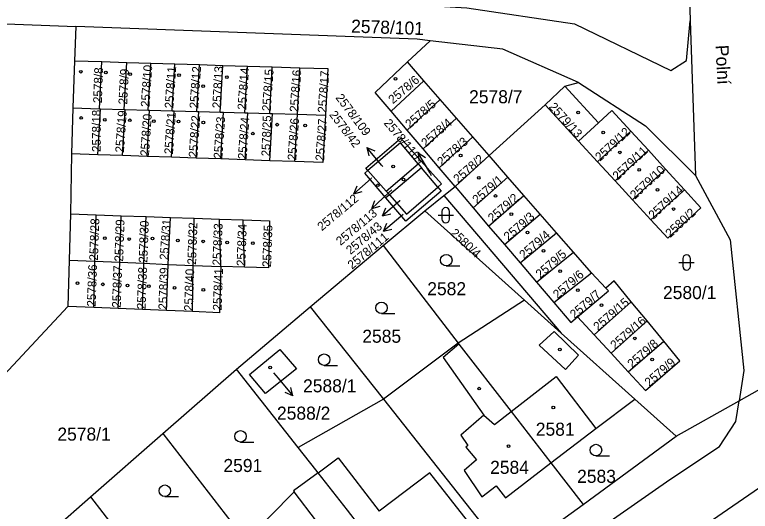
# Model space of a CAD drawing. Extents: x -527335 to -526256, y -1079142 to -1077836.
# Drawn here: x -526700.3 to -526604.5, y -1078355.5 to -1078290.8 of the extents above; entities that cross this region are included whole.
import ezdxf

# ---------------------------------------------------------------- set-up
doc = ezdxf.new("R2010")
doc.units = 0
for name, color, linetype in [('Hranice parcel', 7, 'Continuous'), ('Parcelní čísla', 7, 'Continuous'), ('Pop  PČ popisy', 7, 'Continuous'), ('Vnitřní kresba', 7, 'Continuous'), ('Značky budov', 7, 'Continuous'), ('Značky kultur', 7, 'Continuous')]:
    doc.layers.add(name, color=color, linetype=linetype)

msp = doc.modelspace()

# ---------------------------------------------------------------- linework, layer by layer
at = {"layer": 'Hranice parcel'}
for p, q in [((-526613.4, -1078261.09), (-526612.35, -1078291.6)), ((-526720.03, -1078291.28), (-526692.39, -1078292.33)), ((-526612.35, -1078291.6), (-526611.66, -1078311.76)), ((-526692.39, -1078292.33), (-526692.56, -1078296.81)), ((-526649.16, -1078296.97), (-526646.23, -1078294.21)), ((-526692.56, -1078296.81), (-526692.76, -1078302.96)), ((-526692.56, -1078296.81), (-526688.97, -1078296.92)), ((-526689.31, -1078303.06), (-526688.97, -1078296.92)), ((-526688.97, -1078296.92), (-526685.72, -1078297.02)), ((-526686.06, -1078303.15), (-526685.72, -1078297.02)), ((-526685.72, -1078297.02), (-526682.62, -1078297.12)), ((-526682.96, -1078303.23), (-526682.62, -1078297.12)), ((-526682.62, -1078297.12), (-526679.48, -1078297.22)), ((-526679.81, -1078303.32), (-526679.48, -1078297.22)), ((-526679.48, -1078297.22), (-526676.28, -1078297.32)), ((-526676.61, -1078303.41), (-526676.28, -1078297.32)), ((-526676.28, -1078297.32), (-526673.23, -1078297.41)), ((-526673.56, -1078303.5), (-526673.23, -1078297.41)), ((-526673.23, -1078297.41), (-526670.03, -1078297.51)), ((-526647.04, -1078299.41), (-526649.16, -1078296.97)), ((-526670.36, -1078303.59), (-526670.03, -1078297.51)), ((-526670.03, -1078297.51), (-526666.78, -1078297.61)), ((-526667.12, -1078303.68), (-526666.78, -1078297.61)), ((-526666.78, -1078297.61), (-526663.18, -1078297.72)), ((-526663.52, -1078303.78), (-526663.18, -1078297.72)), ((-526647.04, -1078299.41), (-526651.3, -1078303.4)), ((-526644.92, -1078301.85), (-526647.04, -1078299.41)), ((-526631.23, -1078302.56), (-526628.69, -1078300.14)), ((-526628.69, -1078300.14), (-526626.89, -1078299.64)), ((-526624.28, -1078304.92), (-526628.69, -1078300.14)), ((-526644.92, -1078301.85), (-526649.22, -1078305.85)), ((-526642.8, -1078304.29), (-526644.92, -1078301.85)), ((-526692.76, -1078302.96), (-526692.95, -1078308.93)), ((-526692.76, -1078302.96), (-526689.31, -1078303.06)), ((-526689.49, -1078309.05), (-526689.16, -1078303.06)), ((-526689.31, -1078303.06), (-526689.16, -1078303.06)), ((-526689.16, -1078303.06), (-526686.06, -1078303.15)), ((-526686.29, -1078309.16), (-526685.96, -1078303.15)), ((-526686.06, -1078303.15), (-526685.96, -1078303.15)), ((-526685.96, -1078303.15), (-526682.96, -1078303.23)), ((-526683.1, -1078309.27), (-526682.76, -1078303.24)), ((-526682.96, -1078303.23), (-526682.76, -1078303.24)), ((-526682.76, -1078303.24), (-526679.81, -1078303.32)), ((-526638.55, -1078309.17), (-526631.23, -1078302.56)), ((-526631.23, -1078302.56), (-526626.89, -1078307.29)), ((-526679.9, -1078309.38), (-526679.56, -1078303.33)), ((-526679.81, -1078303.32), (-526679.56, -1078303.33)), ((-526679.56, -1078303.33), (-526676.61, -1078303.41)), ((-526676.7, -1078309.5), (-526676.36, -1078303.42)), ((-526676.61, -1078303.41), (-526676.36, -1078303.42)), ((-526676.36, -1078303.42), (-526673.56, -1078303.5)), ((-526673.56, -1078303.5), (-526673.14, -1078303.51)), ((-526673.48, -1078309.61), (-526673.14, -1078303.51)), ((-526673.14, -1078303.51), (-526670.36, -1078303.59)), ((-526670.36, -1078303.59), (-526669.96, -1078303.6)), ((-526670.3, -1078309.72), (-526669.96, -1078303.6)), ((-526669.96, -1078303.6), (-526667.12, -1078303.68)), ((-526667.12, -1078303.68), (-526666.77, -1078303.69)), ((-526667.11, -1078309.83), (-526666.77, -1078303.69)), ((-526666.77, -1078303.69), (-526663.52, -1078303.78)), ((-526663.86, -1078309.94), (-526663.52, -1078303.78)), ((-526663.52, -1078303.78), (-526659.87, -1078303.88)), ((-526649.22, -1078305.85), (-526651.3, -1078303.4)), ((-526642.8, -1078304.29), (-526647.14, -1078308.3)), ((-526640.68, -1078306.73), (-526642.8, -1078304.29)), ((-526624.28, -1078304.92), (-526626.89, -1078307.29)), ((-526647.14, -1078308.3), (-526649.22, -1078305.85)), ((-526620.09, -1078305.97), (-526624.41, -1078309.98)), ((-526617.79, -1078308.48), (-526620.09, -1078305.97)), ((-526640.68, -1078306.73), (-526645.06, -1078310.75)), ((-526638.55, -1078309.17), (-526640.68, -1078306.73)), ((-526626.89, -1078307.29), (-526624.41, -1078309.98)), ((-526692.95, -1078308.93), (-526693.08, -1078316.77)), ((-526689.49, -1078309.05), (-526692.95, -1078308.93)), ((-526645.06, -1078310.75), (-526647.14, -1078308.3)), ((-526617.79, -1078308.48), (-526622.14, -1078312.45)), ((-526615.55, -1078310.93), (-526617.79, -1078308.48)), ((-526686.29, -1078309.16), (-526689.49, -1078309.05)), ((-526683.1, -1078309.27), (-526686.29, -1078309.16)), ((-526679.9, -1078309.38), (-526683.1, -1078309.27)), ((-526676.7, -1078309.5), (-526679.9, -1078309.38)), ((-526673.48, -1078309.61), (-526676.7, -1078309.5)), ((-526670.3, -1078309.72), (-526673.48, -1078309.61)), ((-526667.11, -1078309.83), (-526670.3, -1078309.72)), ((-526663.86, -1078309.94), (-526667.11, -1078309.83)), ((-526647.8, -1078310.22), (-526647.4, -1078309.88)), ((-526642.98, -1078313.2), (-526638.55, -1078309.17)), ((-526636.1, -1078311.97), (-526638.55, -1078309.17)), ((-526651.94, -1078313.8), (-526647.8, -1078310.22)), ((-526647.34, -1078310.76), (-526651.51, -1078314.29)), ((-526647.8, -1078310.22), (-526647.34, -1078310.76)), ((-526645.22, -1078313.27), (-526647.34, -1078310.76)), ((-526642.98, -1078313.2), (-526645.06, -1078310.75)), ((-526624.41, -1078309.98), (-526622.14, -1078312.45)), ((-526654.33, -1078311.11), (-526651.94, -1078313.8)), ((-526619.86, -1078314.93), (-526615.55, -1078310.93)), ((-526613.1, -1078313.61), (-526615.55, -1078310.93)), ((-526640.62, -1078315.97), (-526636.1, -1078311.97)), ((-526634.01, -1078314.38), (-526636.1, -1078311.97)), ((-526622.14, -1078312.45), (-526619.86, -1078314.93)), ((-526644.44, -1078314.38), (-526642.98, -1078313.2)), ((-526642.98, -1078313.2), (-526640.62, -1078315.97)), ((-526617.46, -1078317.54), (-526613.1, -1078313.61)), ((-526651.51, -1078314.29), (-526651.98, -1078314.69)), ((-526651.51, -1078314.29), (-526651.94, -1078313.8)), ((-526646.9, -1078316.38), (-526644.44, -1078314.38)), ((-526644.44, -1078314.38), (-526629.16, -1078332.29)), ((-526638.6, -1078318.35), (-526634.01, -1078314.38)), ((-526631.88, -1078316.82), (-526634.01, -1078314.38)), ((-526619.86, -1078314.93), (-526617.46, -1078317.54)), ((-526652.33, -1078320.86), (-526646.9, -1078316.38)), ((-526633.94, -1078328), (-526646.9, -1078316.38)), ((-526640.62, -1078315.97), (-526638.6, -1078318.35)), ((-526693.08, -1078316.77), (-526693.26, -1078322.79)), ((-526693.08, -1078316.77), (-526689.74, -1078316.89)), ((-526689.91, -1078322.93), (-526689.74, -1078316.89)), ((-526689.74, -1078316.89), (-526686.49, -1078317)), ((-526686.65, -1078323.07), (-526686.49, -1078317)), ((-526686.49, -1078317), (-526683.2, -1078317.11)), ((-526683.5, -1078323.2), (-526683.2, -1078317.11)), ((-526683.2, -1078317.11), (-526680.06, -1078317.22)), ((-526680.35, -1078323.34), (-526680.06, -1078317.22)), ((-526680.06, -1078317.22), (-526676.96, -1078317.33)), ((-526677.1, -1078323.48), (-526676.96, -1078317.33)), ((-526676.96, -1078317.33), (-526673.67, -1078317.44)), ((-526673.67, -1078317.44), (-526670.57, -1078317.55)), ((-526673.47, -1078323.63), (-526673.67, -1078317.44)), ((-526670.39, -1078323.7), (-526670.57, -1078317.55)), ((-526636.54, -1078320.77), (-526631.88, -1078316.82)), ((-526629.77, -1078319.23), (-526631.88, -1078316.82)), ((-526638.6, -1078318.35), (-526636.54, -1078320.77)), ((-526634.51, -1078323.15), (-526629.77, -1078319.23)), ((-526627.56, -1078321.77), (-526629.77, -1078319.23)), ((-526661.84, -1078328.88), (-526652.33, -1078320.86)), ((-526652.33, -1078320.86), (-526642.59, -1078333.62)), ((-526636.54, -1078320.77), (-526634.51, -1078323.15)), ((-526632.38, -1078325.66), (-526627.56, -1078321.77)), ((-526625.21, -1078324.46), (-526627.56, -1078321.77)), ((-526693.26, -1078322.79), (-526693.43, -1078328.83)), ((-526693.26, -1078322.79), (-526689.91, -1078322.93)), ((-526690.03, -1078328.97), (-526689.91, -1078322.93)), ((-526689.91, -1078322.93), (-526686.65, -1078323.07)), ((-526686.87, -1078329.1), (-526686.65, -1078323.07)), ((-526686.65, -1078323.07), (-526683.5, -1078323.2)), ((-526683.71, -1078329.22), (-526683.5, -1078323.2)), ((-526683.5, -1078323.2), (-526680.35, -1078323.34)), ((-526680.56, -1078329.34), (-526680.35, -1078323.34)), ((-526680.35, -1078323.34), (-526677.1, -1078323.48)), ((-526634.51, -1078323.15), (-526632.38, -1078325.66)), ((-526677.2, -1078329.49), (-526677.1, -1078323.48)), ((-526677.1, -1078323.48), (-526673.47, -1078323.63)), ((-526670.39, -1078323.7), (-526673.47, -1078323.63)), ((-526630.12, -1078328.32), (-526625.21, -1078324.46)), ((-526623.32, -1078326.45), (-526625.21, -1078324.46)), ((-526632.38, -1078325.66), (-526630.12, -1078328.32)), ((-526633.94, -1078328), (-526642.59, -1078333.62)), ((-526629.16, -1078332.29), (-526633.94, -1078328)), ((-526693.43, -1078328.83), (-526701.71, -1078337.73)), ((-526690.03, -1078328.97), (-526693.43, -1078328.83)), ((-526686.87, -1078329.1), (-526690.03, -1078328.97)), ((-526683.71, -1078329.22), (-526686.87, -1078329.1)), ((-526671.45, -1078336.99), (-526661.84, -1078328.88)), ((-526661.84, -1078328.88), (-526652.31, -1078340.92)), ((-526624.86, -1078332.51), (-526620.02, -1078328.21)), ((-526617.96, -1078330.71), (-526620.02, -1078328.21)), ((-526680.56, -1078329.34), (-526683.71, -1078329.22)), ((-526677.2, -1078329.49), (-526680.56, -1078329.34)), ((-526627.02, -1078330.16), (-526624.86, -1078332.51)), ((-526617.96, -1078330.71), (-526622.65, -1078334.92)), ((-526615.79, -1078333.35), (-526617.96, -1078330.71)), ((-526629.16, -1078332.29), (-526619.54, -1078340.92)), ((-526624.86, -1078332.51), (-526622.65, -1078334.92)), ((-526642.59, -1078333.62), (-526652.31, -1078340.92)), ((-526620.42, -1078337.34), (-526615.79, -1078333.35)), ((-526622.65, -1078334.92), (-526620.42, -1078337.34)), ((-526681.04, -1078345.37), (-526671.45, -1078336.99)), ((-526663.41, -1078347.2), (-526671.45, -1078336.99)), ((-526652.31, -1078340.92), (-526663.41, -1078347.2)), ((-526652.31, -1078340.92), (-526635.98, -1078361.55)), ((-526619.54, -1078340.92), (-526614.17, -1078345.74)), ((-526614.17, -1078345.74), (-526605.97, -1078341.1)), ((-526690.48, -1078353.62), (-526681.04, -1078345.37)), ((-526681.04, -1078345.37), (-526670.21, -1078359.37)), ((-526626.29, -1078354.62), (-526614.17, -1078345.74)), ((-526630.48, -1078349.21), (-526626.29, -1078354.62)), ((-526699.79, -1078361.79), (-526690.48, -1078353.62)), ((-526690.48, -1078353.62), (-526683.67, -1078362.36)), ((-526635.98, -1078361.55), (-526626.29, -1078354.62))]:
    msp.add_line(p, q, dxfattribs=at)
for points in [[(-526695.92, -1078285.82), (-526696.17, -1078286.6), (-526641.44, -1078289.9), (-526627.42, -1078292.02), (-526614.86, -1078298.09), (-526612.81, -1078296.77), (-526612.35, -1078291.6)], [(-526646.23, -1078294.21), (-526647.91, -1078294.02), (-526692.39, -1078292.33)], [(-526626.89, -1078299.64), (-526636.74, -1078295.3), (-526646.23, -1078294.21)], [(-526651.3, -1078303.4), (-526653.38, -1078300.95), (-526649.16, -1078296.97)], [(-526663.18, -1078297.72), (-526659.54, -1078297.84), (-526659.87, -1078303.88)], [(-526626.89, -1078299.64), (-526618.17, -1078305.28), (-526611.66, -1078311.76)], [(-526659.87, -1078303.88), (-526660.21, -1078310.07), (-526663.86, -1078309.94)], [(-526620.09, -1078305.97), (-526622.54, -1078303.29), (-526624.28, -1078304.92)], [(-526654.33, -1078311.11), (-526654.59, -1078310.82), (-526650.04, -1078306.89), (-526647.4, -1078309.88)], [(-526647.8, -1078310.22), (-526650.1, -1078307.51), (-526654.33, -1078311.11)], [(-526647.4, -1078309.88), (-526644.75, -1078312.86), (-526645.22, -1078313.27)], [(-526651.98, -1078314.69), (-526654.74, -1078311.46), (-526654.33, -1078311.11)], [(-526611.66, -1078311.76), (-526607.16, -1078320.16), (-526605.36, -1078337.18), (-526605.97, -1078341.1)], [(-526645.22, -1078313.27), (-526644.77, -1078313.8), (-526649.38, -1078317.72), (-526651.98, -1078314.69)], [(-526651.51, -1078314.29), (-526649.29, -1078316.79), (-526645.22, -1078313.27)], [(-526613.1, -1078313.61), (-526610.95, -1078315.97), (-526615.26, -1078319.93), (-526617.46, -1078317.54)], [(-526670.57, -1078317.55), (-526667.15, -1078317.67), (-526667.26, -1078323.78), (-526670.39, -1078323.7)], [(-526673.47, -1078323.63), (-526673.67, -1078329.63), (-526677.2, -1078329.49)], [(-526538.39, -1078327.72), (-526540.03, -1078327.15), (-526546.04, -1078326.1), (-526550.79, -1078326.44), (-526558.7, -1078329.17), (-526588.71, -1078343.39), (-526596.49, -1078347.76), (-526612.22, -1078358.58), (-526630.45, -1078371.95), (-526674.07, -1078406.52), (-526700.09, -1078429.86), (-526748.62, -1078475.19)], [(-526620.02, -1078328.21), (-526622.27, -1078325.47), (-526623.32, -1078326.45)], [(-526627.02, -1078330.16), (-526623.01, -1078326.8), (-526623.32, -1078326.45)], [(-526630.12, -1078328.32), (-526627.91, -1078330.91), (-526627.02, -1078330.16)], [(-526642.59, -1078333.62), (-526642.49, -1078333.75), (-526635.67, -1078342.52), (-526630.48, -1078349.21)], [(-526620.42, -1078337.34), (-526618.18, -1078339.77), (-526613.7, -1078335.9), (-526615.79, -1078333.35)], [(-526663.65, -1078336.93), (-526667.65, -1078340.17), (-526669.74, -1078337.68), (-526665.81, -1078334.44), (-526663.65, -1078336.93)], [(-526605.97, -1078341.1), (-526595.52, -1078335.19), (-526593.56, -1078334.08)], [(-526630.48, -1078349.21), (-526624.62, -1078344.7), (-526619.54, -1078340.92)], [(-526660.83, -1078350.48), (-526661.12, -1078350.11), (-526663.41, -1078347.2)], [(-526660.83, -1078350.48), (-526664.04, -1078352.82), (-526663.93, -1078352.97), (-526670.21, -1078359.37)], [(-526646.41, -1078369.36), (-526650.13, -1078364.49), (-526655.4, -1078357.43), (-526656.98, -1078355.37), (-526660.83, -1078350.48)]]:
    msp.add_lwpolyline(points, dxfattribs=at)
at = {"layer": 'Pop  PČ popisy'}
for p, q in [((-526652.54, -1078310.4), (-526654.469, -1078308.101)), ((-526654.469, -1078308.101), (-526653.442, -1078308.546)), ((-526654.469, -1078308.101), (-526654.209, -1078309.19)), ((-526646.27, -1078311.39), (-526647.77, -1078308.791)), ((-526647.77, -1078308.791), (-526646.836, -1078309.408)), ((-526647.77, -1078308.791), (-526647.703, -1078309.909)), ((-526652.37, -1078310.6), (-526652.54, -1078310.4)), ((-526646.04, -1078311.79), (-526646.27, -1078311.39)), ((-526653.92, -1078312.15), (-526656.15, -1078314.158)), ((-526653.85, -1078312.08), (-526653.92, -1078312.15)), ((-526656.15, -1078314.158), (-526655.741, -1078313.116)), ((-526651.22, -1078313.64), (-526651.63, -1078314.02)), ((-526656.15, -1078314.158), (-526655.071, -1078313.86)), ((-526651.63, -1078314.02), (-526653.825, -1078316.067)), ((-526653.825, -1078316.067), (-526653.434, -1078315.017)), ((-526650.16, -1078315.05), (-526652.425, -1078317.019)), ((-526650.11, -1078315.01), (-526650.16, -1078315.05)), ((-526653.825, -1078316.067), (-526652.751, -1078315.75)), ((-526652.425, -1078317.019), (-526651.998, -1078315.984)), ((-526652.425, -1078317.019), (-526651.341, -1078316.74)), ((-526650.02, -1078317.09), (-526652.319, -1078319.019)), ((-526649.74, -1078316.86), (-526650.02, -1078317.09)), ((-526652.319, -1078319.019), (-526651.874, -1078317.992)), ((-526652.319, -1078319.019), (-526651.23, -1078318.759)), ((-526666.61, -1078337.48), (-526666.03, -1078338.17)), ((-526666.03, -1078338.17), (-526664.101, -1078340.469)), ((-526664.101, -1078340.469), (-526664.361, -1078339.38)), ((-526664.101, -1078340.469), (-526665.128, -1078340.024))]:
    msp.add_line(p, q, dxfattribs=at)
at = {"layer": 'Vnitřní kresba'}
for p, q in [((-526632.02, -1078333.85), (-526630.07, -1078332.1)), ((-526630.07, -1078332.1), (-526626.89, -1078335.15)), ((-526642.49, -1078333.75), (-526644.53, -1078335.48)), ((-526628.6, -1078337.05), (-526632.02, -1078333.85)), ((-526644.53, -1078335.48), (-526639.22, -1078342.99)), ((-526626.89, -1078335.15), (-526628.6, -1078337.05)), ((-526635.67, -1078342.52), (-526629.79, -1078337.93)), ((-526629.79, -1078337.93), (-526624.62, -1078344.7)), ((-526606.39, -1078343.8), (-526605.97, -1078341.1)), ((-526637.83, -1078344.21), (-526635.67, -1078342.52)), ((-526639.22, -1078342.99), (-526642.22, -1078345.58)), ((-526639.22, -1078342.99), (-526637.83, -1078344.21)), ((-526608.53, -1078347.08), (-526606.39, -1078343.8)), ((-526642.22, -1078345.58), (-526641.31, -1078346.93)), ((-526641.31, -1078346.93), (-526641.57, -1078347.13)), ((-526641.57, -1078347.13), (-526640.18, -1078348.82)), ((-526615, -1078351.38), (-526608.53, -1078347.08)), ((-526660.83, -1078350.48), (-526658.21, -1078348.55)), ((-526658.21, -1078348.55), (-526652.85, -1078355.49)), ((-526640.18, -1078348.82), (-526641.81, -1078350.21)), ((-526636.41, -1078353.77), (-526630.48, -1078349.21)), ((-526646.28, -1078350.48), (-526652.85, -1078355.49)), ((-526640.86, -1078357.35), (-526646.28, -1078350.48)), ((-526641.81, -1078350.21), (-526639.49, -1078353.6)), ((-526635.99, -1078365.95), (-526615, -1078351.38)), ((-526661.04, -1078356.81), (-526663.93, -1078352.97)), ((-526639.49, -1078353.6), (-526637.62, -1078352.18)), ((-526637.62, -1078352.18), (-526636.41, -1078353.77))]:
    msp.add_line(p, q, dxfattribs=at)
at = {"layer": 'Značky budov'}
for centre in [(-526691.717, -1078298.239), (-526688.477, -1078298.339), (-526685.287, -1078298.559), (-526678.937, -1078298.699), (-526672.687, -1078298.949), (-526650.727, -1078299.179), (-526675.787, -1078300.129), (-526691.667, -1078304.269), (-526626.957, -1078303.559), (-526688.617, -1078304.519), (-526685.337, -1078304.569), (-526682.227, -1078304.669), (-526679.017, -1078304.719), (-526675.767, -1078304.869), (-526666.147, -1078305.139), (-526662.517, -1078305.249), (-526623.667, -1078306.149), (-526669.327, -1078306.309), (-526642.247, -1078309.169), (-526621.507, -1078308.749), (-526651.027, -1078310.599), (-526618.977, -1078311.009), (-526649.697, -1078312.279), (-526639.897, -1078312.069), (-526653.027, -1078313.039), (-526616.597, -1078313.629), (-526637.707, -1078314.429), (-526635.647, -1078316.789), (-526614.507, -1078316.129), (-526633.547, -1078319.179), (-526688.587, -1078319.919), (-526685.417, -1078320.039), (-526682.381, -1078319.977), (-526679.077, -1078320.239), (-526675.797, -1078320.339), (-526672.667, -1078320.499), (-526669.307, -1078320.579), (-526631.457, -1078321.589), (-526629.287, -1078324.209), (-526692.167, -1078325.779), (-526688.867, -1078325.939), (-526685.647, -1078326.089), (-526682.857, -1078326.179), (-526679.507, -1078326.399), (-526675.767, -1078326.659), (-526626.977, -1078326.709), (-526623.897, -1078328.649), (-526619.557, -1078332.979), (-526629.337, -1078334.419), (-526617.287, -1078335.729), (-526667.067, -1078336.769), (-526639.837, -1078339.529), (-526630.177, -1078341.969), (-526635.997, -1078347.029)]:
    msp.add_circle(centre, 0.175, dxfattribs=at)
at = {"layer": 'Značky kultur'}
for p, q in [((-526644.691, -1078316.441), (-526644.691, -1078317.442)), ((-526643.689, -1078317.442), (-526643.689, -1078316.441)), ((-526645.191, -1078316.941), (-526643.189, -1078316.941)), ((-526613.821, -1078323.081), (-526611.819, -1078323.081)), ((-526613.321, -1078322.581), (-526613.321, -1078323.582)), ((-526612.319, -1078323.582), (-526612.319, -1078322.581)), ((-526644.123, -1078323.54), (-526642.373, -1078323.54)), ((-526652.563, -1078329.75), (-526650.813, -1078329.75)), ((-526660.033, -1078336.5), (-526658.283, -1078336.5)), ((-526670.923, -1078346.49), (-526669.173, -1078346.49)), ((-526624.623, -1078348.28), (-526622.873, -1078348.28)), ((-526680.773, -1078353.58), (-526679.023, -1078353.58))]:
    msp.add_line(p, q, dxfattribs=at)
for centre in [(-526644.123, -1078322.79), (-526652.563, -1078329), (-526660.033, -1078335.75), (-526670.923, -1078345.74), (-526624.623, -1078347.53), (-526680.773, -1078352.83)]:
    msp.add_circle(centre, 0.75, dxfattribs=at)
for centre, start, end in [((-526644.19, -1078316.441), 0, 180), ((-526644.19, -1078317.441), 180, 359.98789), ((-526612.82, -1078322.581), 0, 180), ((-526612.82, -1078323.581), 180, 359.98789)]:
    msp.add_arc(centre, 0.5, start, end, dxfattribs=at)

# ---------------------------------------------------------------- texts
at = {"layer": 'Parcelní čísla'}
for s, height, rotation, p in [('2578/101', 1.7, 358, (-526656.539, -1078293.139)), ('2578/10', 1.14, 86, (-526682.791, -1078302.889)), ('2578/8', 1.139, 88, (-526688.988, -1078302.353)), ('2578/9', 1.139, 87, (-526685.697, -1078302.541)), ('2578/11', 1.14, 86, (-526679.681, -1078303.069)), ('2578/12', 1.14, 86, (-526676.441, -1078303.069)), ('2578/13', 1.139, 87, (-526673.465, -1078303.037)), ('2578/14', 1.14, 86, (-526670.191, -1078303.249)), ('2578/15', 1.14, 86, (-526666.991, -1078303.429)), ('2578/16', 1.14, 86, (-526663.391, -1078303.529)), ('2578/17', 1.14, 86, (-526659.741, -1078303.629)), ('2578/6', 1.139, 40, (-526651.08, -1078302.489)), ('2578/109', 1.14, 307, (-526658.605, -1078301.643)), ('2578/5', 1.14, 41, (-526648.866, -1078305.68)), ('2579/13', 1.14, 312, (-526630.823, -1078302.871)), ('2578/18', 1.139, 90, (-526689.13, -1078308.701)), ('2578/19', 1.14, 86, (-526686.121, -1078308.819)), ('2578/20', 1.14, 86, (-526682.861, -1078309.269)), ('2578/21', 1.14, 86, (-526679.731, -1078309.039)), ('2578/22', 1.14, 86, (-526676.551, -1078309.459)), ('2578/23', 1.14, 86, (-526673.301, -1078309.619)), ('2578/25', 1.1, 88, (-526667.107, -1078309.271)), ('2578/42', 1.14, 307, (-526659.425, -1078303.843)), ('2578/24', 1.14, 86, (-526670.141, -1078309.689)), ('2578/26', 1.14, 86, (-526663.671, -1078309.819)), ('2578/27', 1.14, 86, (-526660.041, -1078309.889)), ('2578/110', 1.14, 310, (-526652.326, -1078304.966)), ('2578/4', 1.14, 41, (-526646.786, -1078308.13)), ('2579/12', 1.14, 43, (-526624.091, -1078309.976)), ('2578/3', 1.14, 41, (-526644.706, -1078310.58)), ('2579/11', 1.14, 43, (-526621.821, -1078312.446)), ('2578/2', 1.14, 41, (-526642.596, -1078312.83)), ('2579/10', 1.14, 43, (-526619.541, -1078314.926)), ('2579/1', 1.14, 41, (-526640.116, -1078315.53)), ('2579/14', 1.14, 43, (-526617.141, -1078317.536)), ('2578/112', 1.14, 40, (-526660.323, -1078319.036)), ('2579/2', 1.14, 41, (-526638.096, -1078317.91)), ('2578/113', 1.14, 40, (-526657.893, -1078320.946)), ('2579/3', 1.14, 41, (-526636.036, -1078320.33)), ('2580/2', 1.14, 43, (-526614.941, -1078319.926)), ('2578/28', 1.14, 88, (-526689.5, -1078322.869)), ('2578/29', 1.14, 88, (-526686.22, -1078322.999)), ('2578/31', 1.1, 86, (-526680.374, -1078322.785)), ('2578/30', 1.14, 88, (-526683.06, -1078323.159)), ('2578/32', 1.14, 88, (-526676.72, -1078323.399)), ('2578/33', 1.14, 88, (-526673.44, -1078323.509)), ('2578/34', 1.14, 88, (-526670.3, -1078323.589)), ('2578/35', 1.14, 88, (-526666.95, -1078323.719)), ('2578/43', 1.14, 40, (-526656.593, -1078322.116)), ('2578/111', 1.14, 40, (-526656.393, -1078324.036)), ('2580/4', 1.14, 317, (-526643.678, -1078319.386)), ('2579/4', 1.14, 41, (-526634.006, -1078322.71)), ('2579/5', 1.14, 41, (-526631.876, -1078325.22)), ('2578/36', 1.14, 88, (-526689.8, -1078328.869)), ('2578/37', 1.14, 88, (-526686.53, -1078329.009)), ('2578/38', 1.14, 88, (-526683.29, -1078329.209)), ('2578/39', 1.14, 88, (-526680.49, -1078329.269)), ('2578/40', 1.14, 88, (-526677.14, -1078329.439)), ('2578/41', 1.14, 88, (-526673.39, -1078329.369)), ('2579/6', 1.14, 41, (-526629.616, -1078327.88)), ('2579/7', 1.14, 41, (-526627.406, -1078330.47)), ('2579/15', 1.14, 41, (-526624.356, -1078332.07)), ('2579/16', 1.14, 41, (-526622.146, -1078334.48)), ('2579/8', 1.14, 41, (-526619.916, -1078336.9)), ('2579/9', 1.14, 41, (-526617.676, -1078339.33))]:
    msp.add_text(s, height=height, rotation=rotation, dxfattribs=at).set_placement(p)
for s, p in [('2578/7', (-526641.15, -1078302.35)), ('2582', (-526646.6, -1078327.36)), ('2580/1', (-526615.89, -1078327.86)), ('2585', (-526655.06, -1078333.55)), ('2588/1', (-526662.775, -1078340.01)), ('2588/2', (-526666.175, -1078343.57)), ('2581', (-526632.459, -1078345.66)), ('2578/1', (-526694.78, -1078346.3)), ('2591', (-526673.15, -1078350.39)), ('2584', (-526638.41, -1078350.63)), ('2583', (-526627.079, -1078351.8))]:
    msp.add_text(s, height=1.7, dxfattribs=at).set_placement(p)
at = {"layer": 'Pop  PČ popisy'}
msp.add_text('Polní', height=1.7, rotation=273, dxfattribs=at).set_placement((-526609.058, -1078294.794))

doc.saveas('drawing.dxf')
